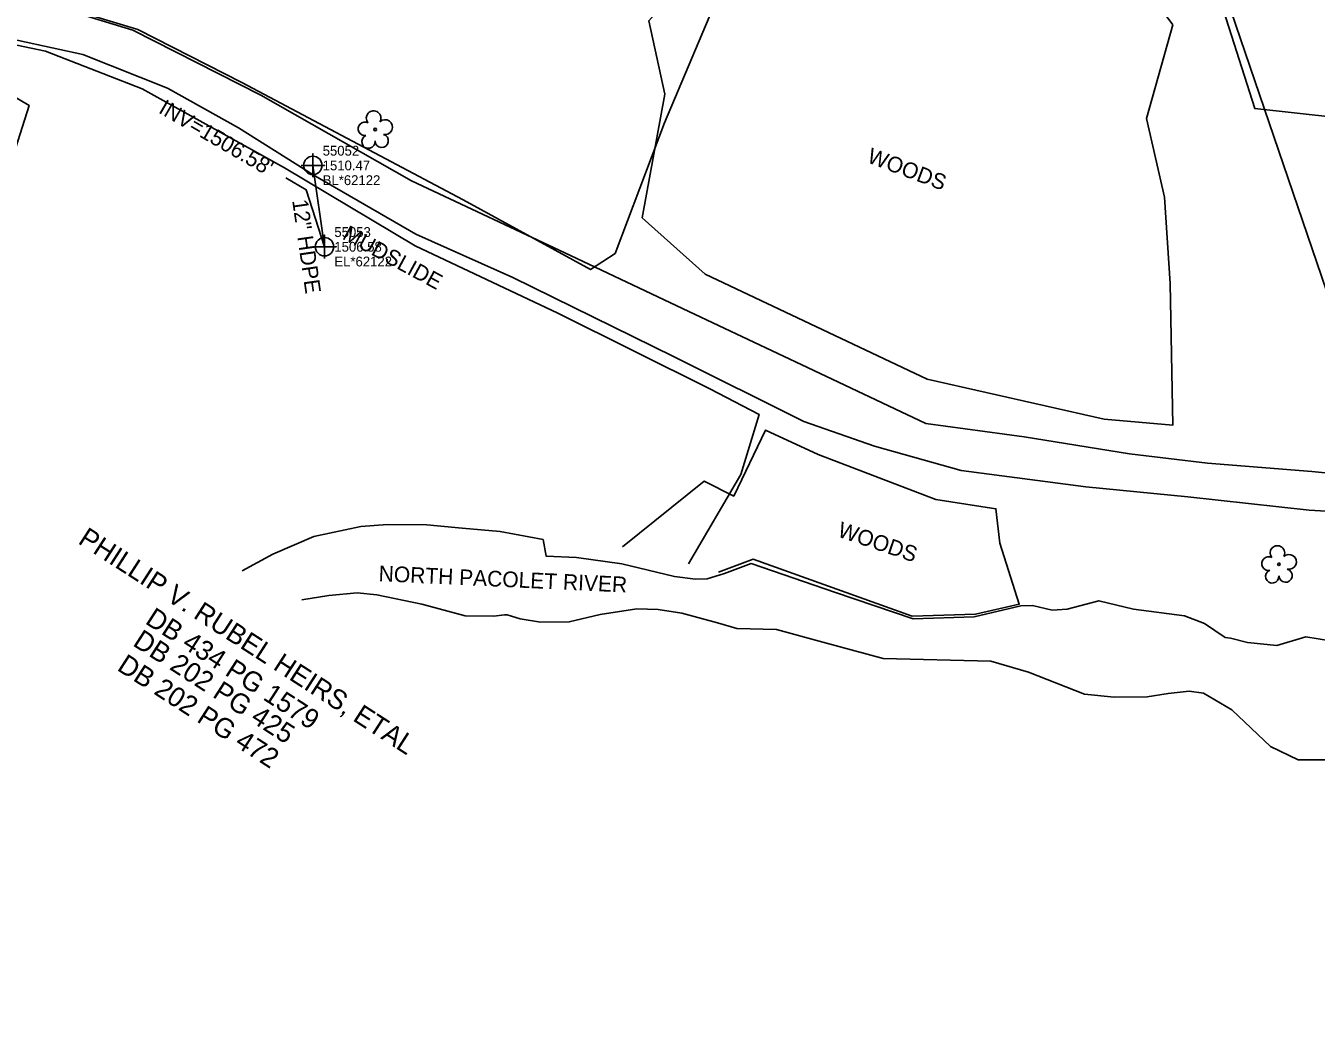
# Model space of a CAD drawing. Extents: x 1004911 to 1009660, y 551419 to 554278.
# Drawn here: x 1007054.2 to 1007382.7, y 551756.1 to 552012.4 of the extents above; entities that cross this region are included whole.
import ezdxf

# ---------------------------------------------------------------- set-up
doc = ezdxf.new("R2010")
doc.units = 0
for name, color, linetype in [('Exist DTM Breakline', 7, 'Continuous'), ('Exist Hydro Jurisdictional Stream or Body of Water', 7, 'Continuous'), ('Exist Hydro Jurisdictional Stream or Body of Water Text', 7, 'Continuous'), ('Exist Other Culture Area Outline Text', 7, 'Continuous'), ('Exist Property Deed Book Text', 7, 'Continuous'), ('Exist Property Line', 7, 'Continuous'), ('Exist Property Owner Text', 7, 'Continuous'), ('Exist Structure Minor Pipes HDPE 12 Inch', 7, 'Continuous'), ('Exist Structure Minor Pipes HDPE 12 Inch Cogo Comment', 7, 'Continuous'), ('Exist Structure Minor Pipes HDPE 12 Inch Cogo Elevation', 7, 'Continuous'), ('Exist Structure Minor Pipes HDPE 12 Inch Cogo Number', 7, 'Continuous'), ('Exist Structure Minor Pipes HDPE 12 Inch Cogo Point CELL', 7, 'Continuous'), ('Exist Structure Minor Pipes HDPE 12 Inch Invert', 7, 'Continuous'), ('Exist Structure Minor Pipes HDPE 12 Inch Leader', 7, 'Continuous'), ('Exist Structure Minor Pipes HDPE 12 Inch Text', 7, 'Continuous'), ('Exist Vegetation Woods Line Text', 7, 'Continuous'), ('Sheet Data Field CELL', 7, 'Continuous'), ('Sheet Plot Border Inside CELL', 7, 'Continuous'), ('Sheet Sticker Incomplete CELL', 7, 'Continuous')]:
    doc.layers.add(name, color=color, linetype=linetype)

msp = doc.modelspace()

# ---------------------------------------------------------------- linework, layer by layer
at = {"layer": 'Exist DTM Breakline'}
for p, q in [((1007143.12, 551986.04), (1007143.12, 551986.04)), ((1007373.23, 551875.29), (1007373.23, 551875.29))]:
    msp.add_line(p, q, dxfattribs=at)
for centre in [(1007143.12, 551986.04), (1007373.23, 551875.29)]:
    msp.add_circle(centre, 0.326, dxfattribs=at)
for centre, radius, start, end in [((1007142.74, 551988.92), 1.86, 330.1651, 219.7134), ((1007140.52, 551986.2), 1.73, 62.6636, 279.3457), ((1007145.67, 551986.63), 1.9, 257.1011, 134.1999), ((1007141.42, 551982.92), 1.69, 111.5671, 6.231), ((1007144.8, 551983.14), 1.7, 181.2822, 74.56), ((1007372.85, 551878.16), 1.86, 330.1651, 219.7134), ((1007370.63, 551875.44), 1.73, 62.6636, 279.3457), ((1007375.78, 551875.88), 1.9, 257.1011, 134.1999), ((1007371.53, 551872.17), 1.69, 111.5671, 6.231), ((1007374.91, 551872.39), 1.7, 181.2822, 74.56)]:
    msp.add_arc(centre, radius, start, end, dxfattribs=at)
at = {"layer": 'Exist Hydro Jurisdictional Stream or Body of Water'}
for points in [[(1007109.3, 551873.58), (1007117.08, 551877.86), (1007127.51, 551882.32), (1007139.46, 551884.88), (1007146.24, 551885.38), (1007156.3, 551885.33), (1007165.3, 551884.44), (1007174.92, 551883.66), (1007185.87, 551881.55), (1007186.64, 551877.37), (1007194.37, 551877.04), (1007205.93, 551875.43), (1007219.38, 551872.2), (1007224.66, 551871.48), (1007227.66, 551871.54), (1007232.08, 551872.97)], [(1007232.08, 551872.97), (1007238.86, 551875.46), (1007260.37, 551868.13), (1007280.08, 551861.35), (1007295.67, 551861.9), (1007307.51, 551864.7), (1007310.47, 551864.78), (1007315.46, 551863.61), (1007319.28, 551863.85), (1007327.39, 551865.98), (1007336.19, 551863.85), (1007349.2, 551862.13), (1007354.27, 551860.18), (1007359.57, 551856.59), (1007360.89, 551856.44), (1007365.26, 551855.35), (1007372.66, 551854.57), (1007380.06, 551856.83), (1007386.38, 551855.74)], [(1007124.47, 551866.25), (1007131.36, 551867.36), (1007138.53, 551867.98), (1007143.53, 551867.53), (1007155.03, 551865.14), (1007166.09, 551862.19), (1007173.32, 551862.03), (1007176.04, 551862.41), (1007176.71, 551862.41), (1007180.04, 551861.36), (1007185.21, 551860.52), (1007192.55, 551860.58), (1007200.44, 551862.53), (1007209.72, 551863.92), (1007215.17, 551863.75), (1007221.23, 551862.79), (1007230.29, 551860.35), (1007235.23, 551858.91), (1007245.29, 551858.69), (1007257.13, 551855.41), (1007272.47, 551851.28), (1007299.87, 551850.62), (1007309.48, 551847.84), (1007323.77, 551842.17), (1007331.27, 551841.39), (1007339.66, 551841.5), (1007345, 551842.39), (1007350.39, 551843), (1007354, 551842.45), (1007361.23, 551838.17), (1007371.06, 551828.88), (1007378.12, 551825.43), (1007394.8, 551825.49)]]:
    msp.add_lwpolyline(points, dxfattribs=at)
at = {"layer": 'Exist Property Line'}
msp.add_line((1007358.84, 552022.71), (1007525.53, 551533), dxfattribs=at)
at = {"layer": 'Exist Structure Minor Pipes HDPE 12 Inch'}
msp.add_line((1007127.27, 551976.87), (1007130.24, 551956.15), dxfattribs=at)
at = {"layer": 'Exist Structure Minor Pipes HDPE 12 Inch Cogo Point CELL'}
for points in [[(1007124.27, 551976.87), (1007130.27, 551976.87), (1007127.27, 551976.87), (1007127.27, 551979.87), (1007127.27, 551973.87)], [(1007127.24, 551956.15), (1007133.24, 551956.15), (1007130.24, 551956.15), (1007130.24, 551959.15), (1007130.24, 551953.15)]]:
    msp.add_lwpolyline(points, dxfattribs=at)
for centre in [(1007127.27, 551976.87), (1007130.24, 551956.15)]:
    msp.add_circle(centre, 2.34, dxfattribs=at)
at = {"layer": 'Exist Structure Minor Pipes HDPE 12 Inch Leader'}
msp.add_lwpolyline([(1007130.24, 551956.15), (1007125.59, 551970.66), (1007120.4, 551973.68)], dxfattribs=at)
at = {"layer": 'Sheet Data Field CELL'}
msp.add_lwpolyline([(1007260.84, 552050.93), (1007231.65, 552022.96), (1007216.79, 551987.75), (1007204.24, 551954.45), (1007197.97, 551950.36), (1007165.51, 551968.1), (1007109.19, 551997.98), (1007082.73, 552011.49), (1007058.8, 552018.7), (1007064.05, 552042.58), (1007087.68, 552056.2), (1007123.48, 552085.57), (1007156.89, 552114.94), (1007188.39, 552090.82), (1007225.57, 552075.51), (1007228.91, 552075.8), (1007249.67, 552066.59)], close=True, dxfattribs=at)
msp.add_lwpolyline([(1007050.38, 551917.54), (1007039.47, 551943.2), (1007055.01, 551992.14), (1007041.37, 552000.2), (1007026.92, 552007.97), (1007042.88, 552009.38), (1007059.24, 552005.97), (1007083.79, 551996.42), (1007120.07, 551976.22), (1007153.34, 551956.43), (1007189.62, 551939.24), (1007228.35, 551920), (1007240.89, 551913.45), (1007236.26, 551898.16), (1007222.89, 551875.37)], dxfattribs=at)
at = {"layer": 'Sheet Plot Border Inside CELL'}
for points in [[(1007409.45, 551986.71), (1007367.09, 551991.34), (1007357.17, 552022.57), (1007384.92, 552041.98)], [(1007206.1, 551879.75), (1007226.87, 551896.46), (1007234.44, 551892.67), (1007242.5, 551909.47), (1007255.91, 551903.22), (1007285.87, 551891.81), (1007301.19, 551889.42), (1007302.18, 551880.63), (1007307.13, 551865.09), (1007295.97, 551862.56), (1007279.86, 551862.08), (1007239.39, 551876.55), (1007230.56, 551873.25)]]:
    msp.add_lwpolyline(points, dxfattribs=at)
msp.add_lwpolyline([(1007227.42, 552030.38), (1007249.33, 552032.93), (1007277.97, 552029.9), (1007335.56, 552027.16), (1007346.23, 552012.7), (1007339.55, 551988.82), (1007344.08, 551968.76), (1007345.51, 551946.79), (1007346.23, 551910.73), (1007328.76, 551912.25), (1007283.66, 551922.47), (1007227.15, 551949.21), (1007211.15, 551963.51), (1007216.89, 551995.03), (1007212.81, 552013.73)], close=True, dxfattribs=at)
at = {"layer": 'Sheet Sticker Incomplete CELL'}
for points in [[(1007405.49, 551896.55), (1007381.64, 551898.94), (1007355.06, 551901.07), (1007335.15, 551903.39), (1007308.34, 551907.71), (1007283.35, 551911.17), (1007253.19, 551925.42), (1007223.02, 551939.67), (1007192.86, 551953.92), (1007152.4, 551972.99), (1007114, 551994.79), (1007081.43, 552011.31), (1007055.59, 552019.32), (1007034.47, 552021.77)], [(1007044.45, 552010.38), (1007068.74, 552005.16), (1007090.3, 551996.54), (1007108.36, 551986.41), (1007127.31, 551974.46), (1007153.49, 551959.39), (1007178.22, 551948.32), (1007219.13, 551928.19), (1007252.25, 551911.61), (1007270.26, 551905.33), (1007292.32, 551899.15), (1007324.06, 551895.04), (1007350.01, 551892.42), (1007380.97, 551889.09), (1007402.48, 551887.75)]]:
    msp.add_lwpolyline(points, dxfattribs=at)

# ---------------------------------------------------------------- texts
at = {"layer": 'Exist Hydro Jurisdictional Stream or Body of Water Text'}
msp.add_text('NORTH PACOLET RIVER', height=4, rotation=357.3858, dxfattribs=at).set_placement((1007143.96, 551870.97))
at = {"layer": 'Exist Other Culture Area Outline Text'}
msp.add_text('MUDSLIDE', height=4, rotation=331.5471, dxfattribs=at).set_placement((1007134.53, 551958.26))
at = {"layer": 'Exist Property Deed Book Text'}
for s, p in [('DB 434 PG 1579', (1007084.32, 551860.33)), ('DB 202 PG 425', (1007081.16, 551854.72)), ('DB 202 PG 472', (1007077.16, 551848.46))]:
    msp.add_text(s, height=5, rotation=327.1766, dxfattribs=at).set_placement(p)
at = {"layer": 'Exist Property Owner Text'}
msp.add_text('PHILLIP V. RUBEL HEIRS, ETAL', height=5, rotation=327.1766, dxfattribs=at).set_placement((1007067.23, 551880.74))
at = {"layer": 'Exist Structure Minor Pipes HDPE 12 Inch Cogo Comment'}
for s, p in [('BL*62122', (1007129.77, 551971.87)), ('EL*62122', (1007132.74, 551951.15))]:
    msp.add_text(s, height=2.5, dxfattribs=at).set_placement(p)
at = {"layer": 'Exist Structure Minor Pipes HDPE 12 Inch Cogo Elevation'}
for s, p in [('1510.47', (1007129.77, 551975.62)), ('1506.58', (1007132.74, 551954.9))]:
    msp.add_text(s, height=2.5, dxfattribs=at).set_placement(p)
at = {"layer": 'Exist Structure Minor Pipes HDPE 12 Inch Cogo Number'}
for s, p in [('55052', (1007129.77, 551979.37)), ('55053', (1007132.74, 551958.65))]:
    msp.add_text(s, height=2.5, dxfattribs=at).set_placement(p)
at = {"layer": 'Exist Structure Minor Pipes HDPE 12 Inch Invert'}
msp.add_text("INV=1506.58'", height=4, rotation=329.7508, dxfattribs=at).set_placement((1007087.74, 551990.42))
at = {"layer": 'Exist Structure Minor Pipes HDPE 12 Inch Text'}
msp.add_text('12" HDPE', height=4, rotation=278.1591, dxfattribs=at).set_placement((1007121.99, 551967.96))
at = {"layer": 'Exist Vegetation Woods Line Text'}
for rotation, p in [(339.4992, (1007268.13, 551977.71)), (341.2806, (1007260.61, 551882.41))]:
    msp.add_text('WOODS', height=4, rotation=rotation, dxfattribs=at).set_placement(p)

doc.saveas('drawing.dxf')
